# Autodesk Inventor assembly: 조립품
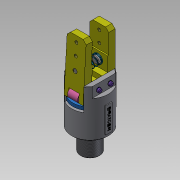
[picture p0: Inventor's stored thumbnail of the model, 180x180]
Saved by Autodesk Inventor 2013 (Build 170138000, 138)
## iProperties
Created: 2019-02
Part Number: 조립품
Document SubType Name: Assembly
Designer: Administrator
Author: Administrator
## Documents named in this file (11)
- C:\Documents and Settings\Administrator\바탕 화면\490207V1004\조립품.iam
- C:\Documents and Settings\Administrator\바탕 화면\490207V1004\O-링.ipt
- C:\Documents and Settings\Administrator\바탕 화면\490207V1004\가이드핀.ipt
- C:\Documents and Settings\Administrator\바탕 화면\490207V1004\본체.ipt
- C:\Documents and Settings\Administrator\바탕 화면\490207V1004\부시.ipt
- C:\Documents and Settings\Administrator\바탕 화면\490207V1004\스프링.ipt
- C:\Documents and Settings\Administrator\바탕 화면\490207V1004\평행핀 6x28.ipt
- C:\Documents and Settings\Administrator\바탕 화면\490207V1004\피스톤.ipt
- C:\Documents and Settings\Administrator\바탕 화면\490207V1004\핀.ipt
- C:\Documents and Settings\Administrator\바탕 화면\490207V1004\핑거.ipt
- C:\Documents and Settings\Administrator\바탕 화면\490207V1004\E-링.ipt
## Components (13 placed, 6 different names)
1. O-링:1
2. 가이드핀:1
3. 피스톤:1
4. 핀:1
5. 핑거:1
6. E-링:1
7. O-링:2
8. 핑거:2
9. 핀:2
10. E-링:2
11. E-링:3
12. E-링:4
13. 가이드핀:2
